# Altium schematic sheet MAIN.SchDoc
size A2
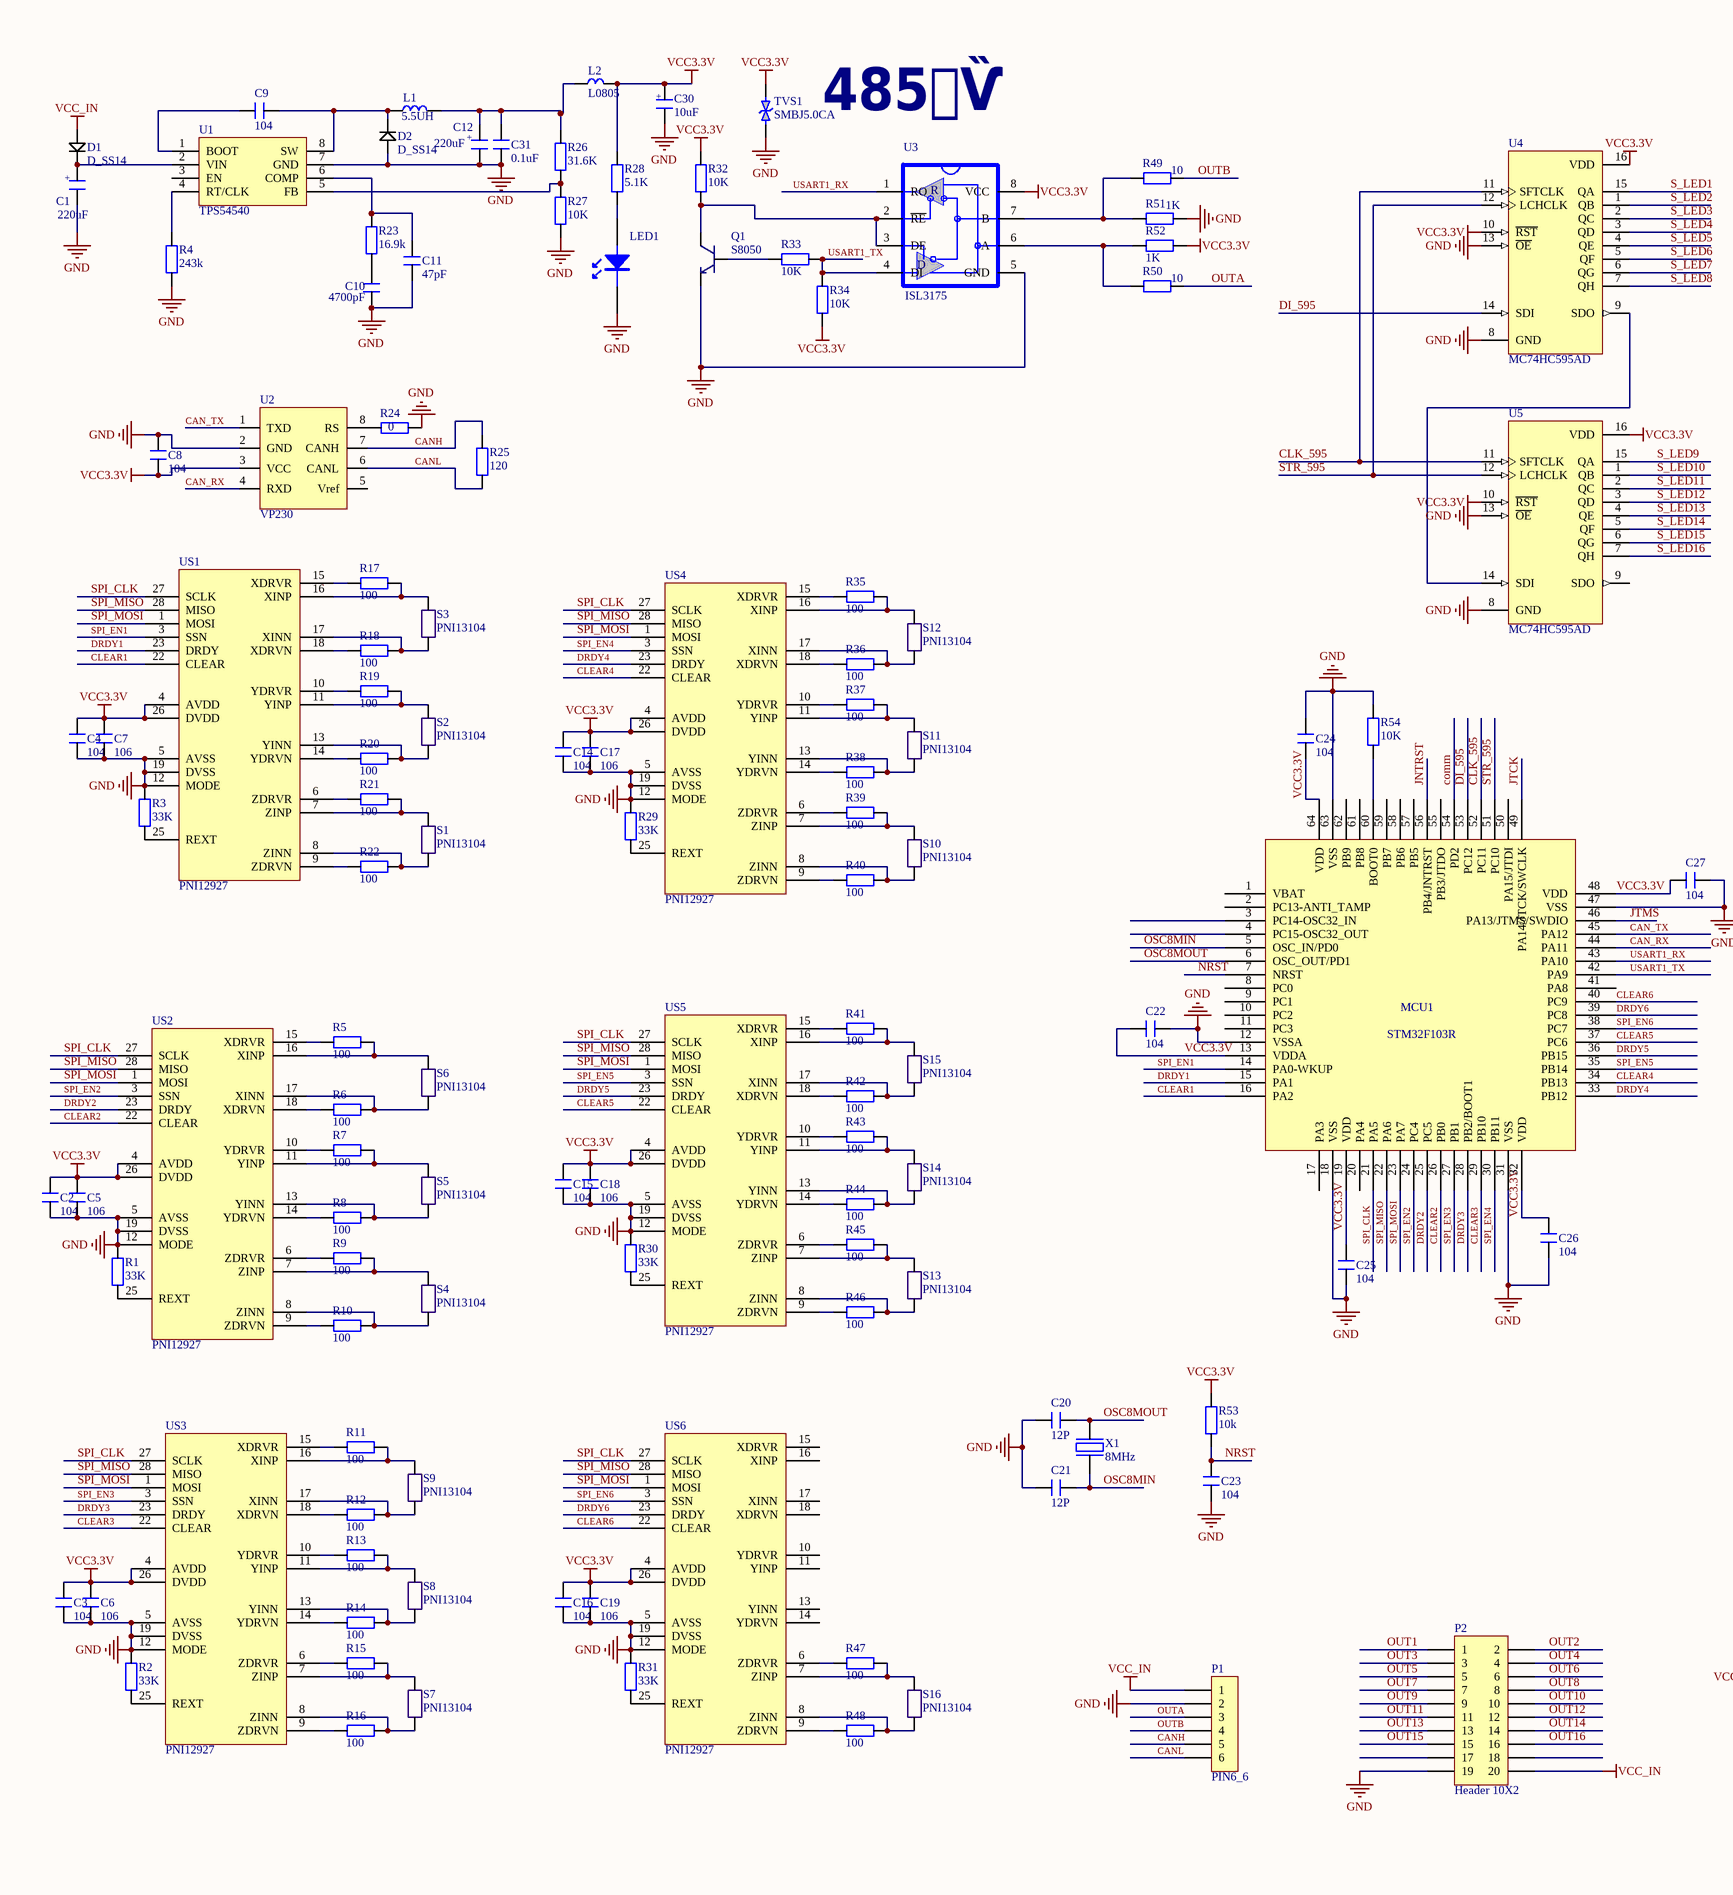
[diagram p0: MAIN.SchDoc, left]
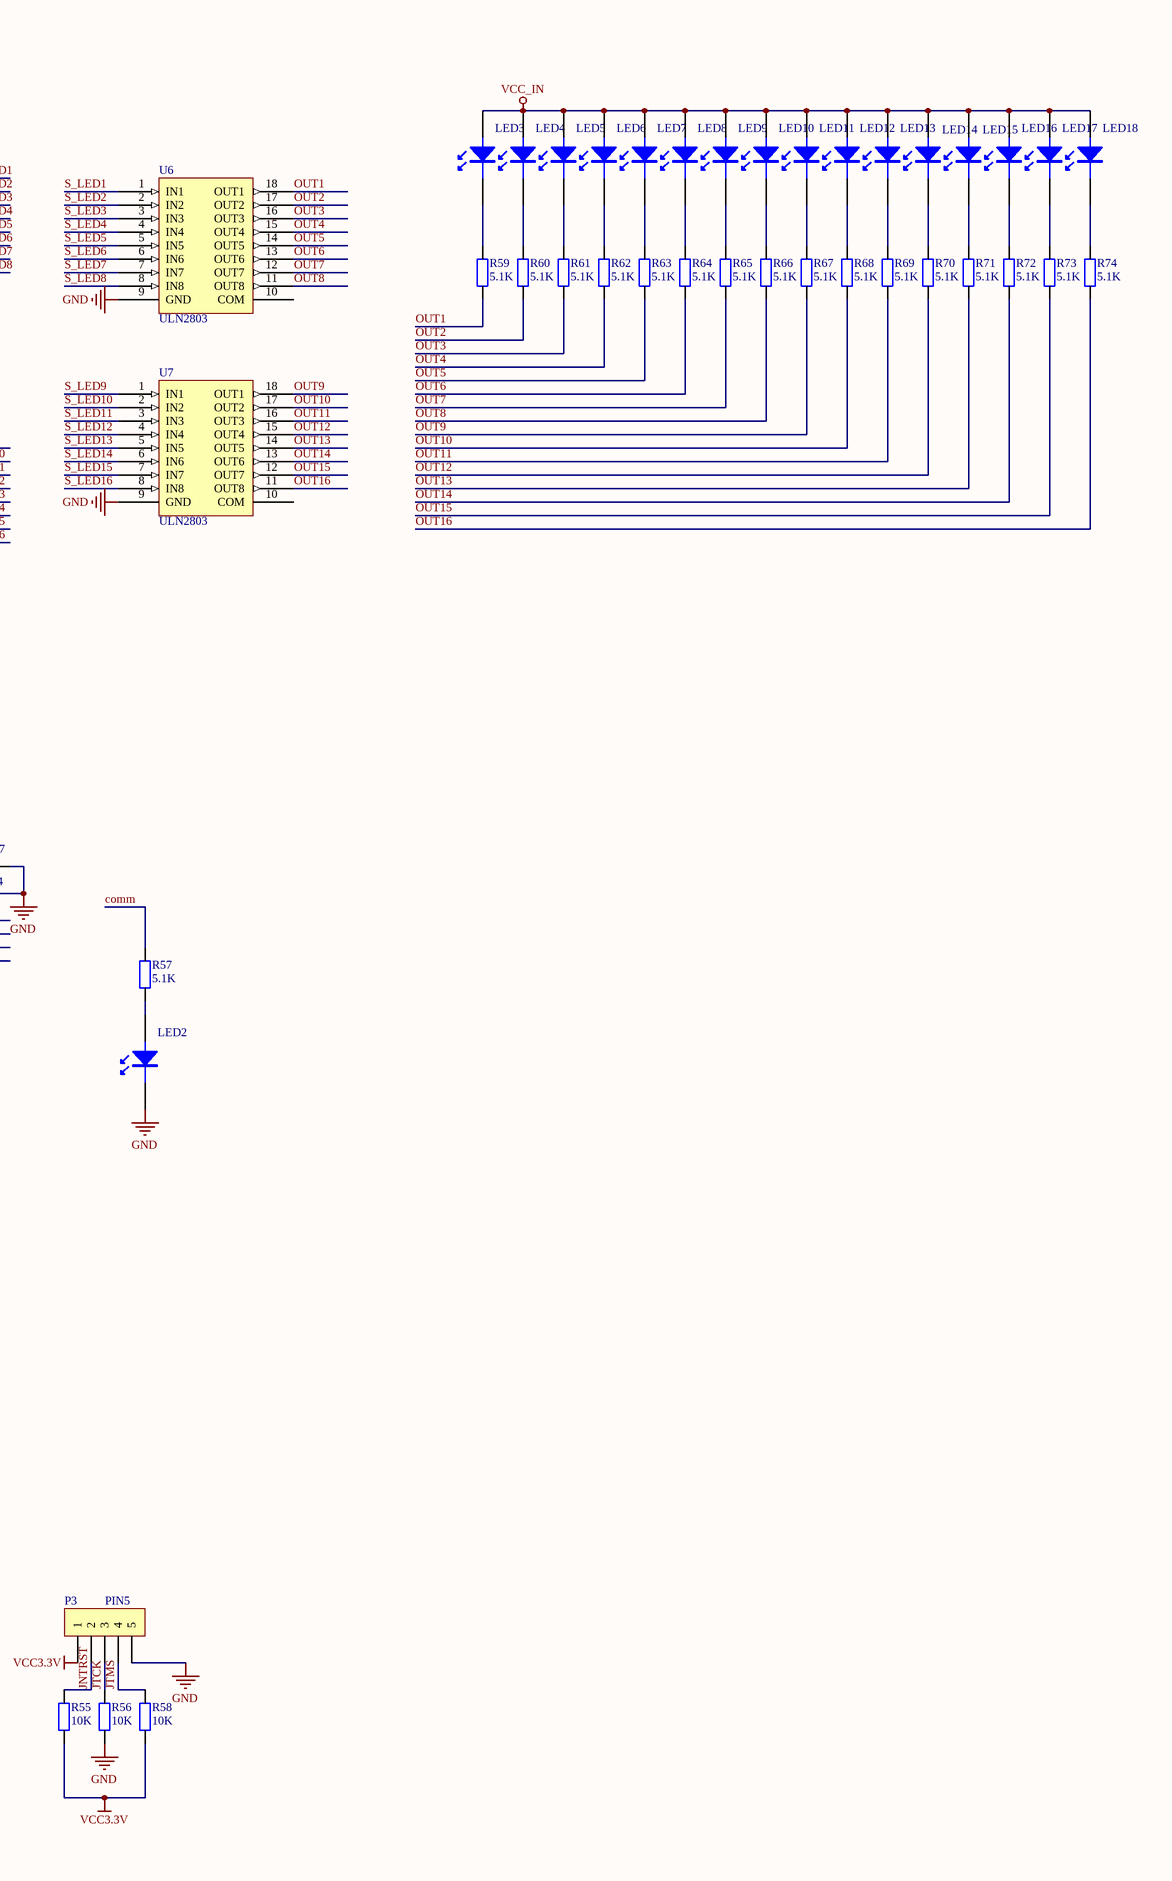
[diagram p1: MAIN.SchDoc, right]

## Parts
C1  220uF  [CAP_SMT_1]
C2  104  [C0603]
C3  104  [C0603]
C4  104  [C0603]
C5  106  [C0805]
C6  106  [C0805]
C7  106  [C0805]
C8  104  [C0603]
C9  104  [C0603]
C10  4700pF  [C0603]
C11  47pF  [C0603]
C12  220uF  [CAP_SMT_1]
C14  104  [C0603]
C15  104  [C0603]
C16  104  [C0603]
C17  106  [C0805]
C18  106  [C0805]
C19  106  [C0805]
C20  12P  [C0603]
C21  12P  [C0603]
C22  104  [C0603]
C23  104  [C0603]
C24  104  [C0603]
C25  104  [C0603]
C26  104  [C0603]
C27  104  [C0603]
C30  10uF  [C1206]
C31  0.1uF  [C0603]
D1  D_SS14  [D_3.0*5.0]
D2  D_SS14  [D_3.0*5.0]
L1  5.5UH  [L7*7]
L2  L0805  [L0805]
LED1  (no value)  [LED1-AK]
LED2  (no value)  [LED1-AK]
LED3  (no value)  [LED1-AK]
LED4  (no value)  [LED1-AK]
LED5  (no value)  [LED1-AK]
LED6  (no value)  [LED1-AK]
LED7  (no value)  [LED1-AK]
LED8  (no value)  [LED1-AK]
LED9  (no value)  [LED1-AK]
LED10  (no value)  [LED1-AK]
LED11  (no value)  [LED1-AK]
LED12  (no value)  [LED1-AK]
LED13  (no value)  [LED1-AK]
LED14  (no value)  [LED1-AK]
LED15  (no value)  [LED1-AK]
LED16  (no value)  [LED1-AK]
LED17  (no value)  [LED1-AK]
LED18  (no value)  [LED1-AK]
MCU1  STM32F103R  [TQFP64_STM32]
P1  PIN6_6  [KF350W_6]
P2  Header 10X2  [PIN20_10*2_2.54MM_1]
P3  PIN5  [PIN5_5*1_2.54MM_2]
Q1  S8050  [SOT-23]
R1  33K  [R0603]
R2  33K  [R0603]
R3  33K  [R0603]
R4  243k  [R0603]
R5  100  [R0603]
R6  100  [R0603]
R7  100  [R0603]
R8  100  [R0603]
R9  100  [R0603]
R10  100  [R0603]
R11  100  [R0603]
R12  100  [R0603]
R13  100  [R0603]
R14  100  [R0603]
R15  100  [R0603]
R16  100  [R0603]
R17  100  [R0603]
R18  100  [R0603]
R19  100  [R0603]
R20  100  [R0603]
R21  100  [R0603]
R22  100  [R0603]
R23  16.9k  [R0603]
R24  0  [R0603]
R25  120  [R0603]
R26  31.6K  [R0603]
R27  10K  [R0603]
R28  5.1K  [R0603]
R29  33K  [R0603]
R30  33K  [R0603]
R31  33K  [R0603]
R32  10K  [R0603]
R33  10K  [R0603]
R34  10K  [R0603]
R35  100  [R0603]
R36  100  [R0603]
R37  100  [R0603]
R38  100  [R0603]
R39  100  [R0603]
R40  100  [R0603]
R41  100  [R0603]
R42  100  [R0603]
R43  100  [R0603]
R44  100  [R0603]
R45  100  [R0603]
R46  100  [R0603]
R47  100  [R0603]
R48  100  [R0603]
R49  10  [R0603]
R50  10  [R0603]
R51  1K  [R0603]
R52  1K  [R0603]
R53  10k  [R0603]
R54  10K  [R0603]
R55  10K  [R0603]
R56  10K  [R0603]
R57  5.1K  [R0603]
R58  10K  [R0603]
R59  5.1K  [R0603]
R60  5.1K  [R0603]
R61  5.1K  [R0603]
R62  5.1K  [R0603]
R63  5.1K  [R0603]
R64  5.1K  [R0603]
R65  5.1K  [R0603]
R66  5.1K  [R0603]
R67  5.1K  [R0603]
R68  5.1K  [R0603]
R69  5.1K  [R0603]
R70  5.1K  [R0603]
R71  5.1K  [R0603]
R72  5.1K  [R0603]
R73  5.1K  [R0603]
R74  5.1K  [R0603]
S1  PNI13104  [PNI-13104]
S2  PNI13104  [PNI-13104]
S3  PNI13104  [PNI-13104]
S4  PNI13104  [PNI-13104]
S5  PNI13104  [PNI-13104]
S6  PNI13104  [PNI-13104]
S7  PNI13104  [PNI-13104]
S8  PNI13104  [PNI-13104]
S9  PNI13104  [PNI-13104]
S10  PNI13104  [PNI-13104]
S11  PNI13104  [PNI-13104]
S12  PNI13104  [PNI-13104]
S13  PNI13104  [PNI-13104]
S14  PNI13104  [PNI-13104]
S15  PNI13104  [PNI-13104]
S16  PNI13104  [PNI-13104]
TVS1  SMBJ5.0CA  [SMBJ6.5CA]
U1  TPS54540  [SOP8_1]
U2  VP230  [SOP8]
U3  ISL3175  [SO-8]
U4  MC74HC595AD  [SOP16]
U5  MC74HC595AD  [sop16]
U6  ULN2803  [SO-G18]
U7  ULN2803  [SO-G18]
US1  PNI12927  [MLF_28]
US2  PNI12927  [MLF_28]
US3  PNI12927  [MLF_28]
US4  PNI12927  [MLF_28]
US5  PNI12927  [MLF_28]
US6  PNI12927  [MLF_28]
X1  8MHz  [XTAL_49SMD]

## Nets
GND: C1.2 C2.1 C3.1 C4.1 C5.1 C6.1 C7.1 C8.2 C10.1 C11.1 C12.2 C14.1 C15.1 C16.1 C17.1 C18.1 C19.1 C20.1 C21.1 C22.2 C23.1 C24.2 C25.1 C26.1 C27.2 C30.2 C31.1 D2.1 LED1.K LED2.K MCU1.12(VSSA) MCU1.18(VSS) MCU1.31(VSS) MCU1.47(VSS) MCU1.63(VSS) P1.2 P2.19 P3.5 Q1.2 R1.2 R2.2 R3.2 R4.1 R24.2 R27.1 R29.2 R30.2 R31.2 R51.1 R54.2 R56.1 TVS1.1 U1.7(GND) U2.2(GND) U3.5(GND) U4.8(GND) U4.13(~{OE}) U5.8(GND) U5.13(~{OE}) U6.9(GND) U7.9(GND) US1.5(AVSS) US1.12(MODE) US1.19(DVSS) US2.5(AVSS) US2.12(MODE) US2.19(DVSS) US3.5(AVSS) US3.12(MODE) US3.19(DVSS) US4.5(AVSS) US4.12(MODE) US4.19(DVSS) US5.5(AVSS) US5.12(MODE) US5.19(DVSS) US6.5(AVSS) US6.12(MODE) US6.19(DVSS)
VCC3.3V: C2.2 C3.2 C4.2 C5.2 C6.2 C7.2 C8.1 C14.2 C15.2 C16.2 C17.2 C18.2 C19.2 C22.1 C24.1 C25.2 C26.2 C27.1 C30.1 L2.2 MCU1.13(VDDA) MCU1.19(VDD) MCU1.32(VDD) MCU1.48(VDD) MCU1.64(VDD) P3.1 R28.2 R32.1 R34.1 R52.1 R53.2 R55.1 R58.1 TVS1.2 U2.3(VCC) U3.8(VCC) U4.10(~{RST}) U4.16(VDD) U5.10(~{RST}) U5.16(VDD) US1.4(AVDD) US1.26(DVDD) US2.4(AVDD) US2.26(DVDD) US3.4(AVDD) US3.26(DVDD) US4.4(AVDD) US4.26(DVDD) US5.4(AVDD) US5.26(DVDD) US6.4(AVDD) US6.26(DVDD)
VCC_IN: D1.1 LED3.A LED4.A LED5.A LED6.A LED7.A LED8.A LED9.A LED10.A LED11.A LED12.A LED13.A LED14.A LED15.A LED16.A LED17.A LED18.A P1.1 P2.20
CAN_RX: MCU1.44(PA11) U2.4(RXD)
CAN_TX: MCU1.45(PA12) U2.1(TXD)
CANH: P1.5 R25.2 U2.7(CANH)
CANL: P1.6 R25.1 U2.6(CANL)
CLEAR1: MCU1.16(PA2) US1.22(CLEAR)
CLEAR2: MCU1.26(PB0) US2.22(CLEAR)
CLEAR3: MCU1.29(PB10) US3.22(CLEAR)
CLEAR4: MCU1.34(PB13) US4.22(CLEAR)
CLEAR5: MCU1.37(PC6) US5.22(CLEAR)
CLEAR6: MCU1.40(PC9) US6.22(CLEAR)
CLK_595: MCU1.52(PC11) U4.11(SFTCLK) U5.11(SFTCLK)
comm: MCU1.54(PD2) R57.2
DI_595: MCU1.53(PC12) U4.14(SDI)
DRDY1: MCU1.15(PA1) US1.23(DRDY)
DRDY2: MCU1.25(PC5) US2.23(DRDY)
DRDY3: MCU1.28(PB2/BOOT1) US3.23(DRDY)
DRDY4: MCU1.33(PB12) US4.23(DRDY)
DRDY5: MCU1.36(PB15) US5.23(DRDY)
DRDY6: MCU1.39(PC8) US6.23(DRDY)
JNTRST: MCU1.56(PB4/JNTRST) P3.2 R55.2
JTCK: MCU1.49(PA14/JTCK/SWCLK) P3.3 R56.2
JTMS: MCU1.46(PA13/JTMS/SWDIO) P3.4 R58.2
NRST: C23.2 MCU1.7(NRST) R53.1
OSC8MIN: C21.2 MCU1.5(OSC_IN/PD0) X1.1
OSC8MOUT: C20.2 MCU1.6(OSC_OUT/PD1) X1.2
OUT1: P2.1 R59.1 U6.18(OUT1)
OUT2: P2.2 R60.1 U6.17(OUT2)
OUT3: P2.3 R61.1 U6.16(OUT3)
OUT4: P2.4 R62.1 U6.15(OUT4)
OUT5: P2.5 R63.1 U6.14(OUT5)
OUT6: P2.6 R64.1 U6.13(OUT6)
OUT7: P2.7 R65.1 U6.12(OUT7)
OUT8: P2.8 R66.1 U6.11(OUT8)
OUT9: P2.9 R67.1 U7.18(OUT1)
OUT10: P2.10 R68.1 U7.17(OUT2)
OUT11: P2.11 R69.1 U7.16(OUT3)
OUT12: P2.12 R70.1 U7.15(OUT4)
OUT13: P2.13 R71.1 U7.14(OUT5)
OUT14: P2.14 R72.1 U7.13(OUT6)
OUT15: P2.15 R73.1 U7.12(OUT7)
OUT16: P2.16 R74.1 U7.11(OUT8)
OUTA: P1.3 R50.1
OUTB: P1.4 R49.1
S_LED1: U4.15(QA) U6.1(IN1)
S_LED2: U4.1(QB) U6.2(IN2)
S_LED3: U4.2(QC) U6.3(IN3)
S_LED4: U4.3(QD) U6.4(IN4)
S_LED5: U4.4(QE) U6.5(IN5)
S_LED6: U4.5(QF) U6.6(IN6)
S_LED7: U4.6(QG) U6.7(IN7)
S_LED8: U4.7(QH) U6.8(IN8)
S_LED9: U5.15(QA) U7.1(IN1)
S_LED10: U5.1(QB) U7.2(IN2)
S_LED11: U5.2(QC) U7.3(IN3)
S_LED12: U5.3(QD) U7.4(IN4)
S_LED13: U5.4(QE) U7.5(IN5)
S_LED14: U5.5(QF) U7.6(IN6)
S_LED15: U5.6(QG) U7.7(IN7)
S_LED16: U5.7(QH) U7.8(IN8)
SPI_CLK: MCU1.21(PA5) US1.27(SCLK) US2.27(SCLK) US3.27(SCLK) US4.27(SCLK) US5.27(SCLK) US6.27(SCLK)
SPI_EN1: MCU1.14(PA0-WKUP) US1.3(SSN)
SPI_EN2: MCU1.24(PC4) US2.3(SSN)
SPI_EN3: MCU1.27(PB1) US3.3(SSN)
SPI_EN4: MCU1.30(PB11) US4.3(SSN)
SPI_EN5: MCU1.35(PB14) US5.3(SSN)
SPI_EN6: MCU1.38(PC7) US6.3(SSN)
SPI_MISO: MCU1.22(PA6) US1.28(MISO) US2.28(MISO) US3.28(MISO) US4.28(MISO) US5.28(MISO) US6.28(MISO)
SPI_MOSI: MCU1.23(PA7) US1.1(MOSI) US2.1(MOSI) US3.1(MOSI) US4.1(MOSI) US5.1(MOSI) US6.1(MOSI)
STR_595: MCU1.51(PC10) U4.12(LCHCLK) U5.12(LCHCLK)
USART1_RX: MCU1.43(PA10) U3.1(RO)
USART1_TX: MCU1.42(PA9) R33.1 R34.2 U3.4(DI)
NetC1_1: C1.1 D1.2 U1.2(VIN)
NetC9_1: C9.1 D2.2 L1.1 U1.8(SW)
NetC9_2: C9.2 U1.1(BOOT)
NetC10_2: C10.2 R23.1
NetC11_2: C11.2 R23.2 U1.6(COMP)
NetC12_1: C12.1 C31.2 L1.2 L2.1 R26.2
NetLED1_A: LED1.A R28.1
NetLED2_A: LED2.A R57.1
NetLED3_K: LED3.K R59.2
NetLED4_K: LED4.K R60.2
NetLED5_K: LED5.K R61.2
NetLED6_K: LED6.K R62.2
NetLED7_K: LED7.K R63.2
NetLED8_K: LED8.K R64.2
NetLED9_K: LED9.K R65.2
NetLED10_K: LED10.K R66.2
NetLED11_K: LED11.K R67.2
NetLED12_K: LED12.K R68.2
NetLED13_K: LED13.K R69.2
NetLED14_K: LED14.K R70.2
NetLED15_K: LED15.K R71.2
NetLED16_K: LED16.K R72.2
NetLED17_K: LED17.K R73.2
NetLED18_K: LED18.K R74.2
NetMCU1_60: MCU1.60(BOOT0) R54.1
NetQ1_1: Q1.1 R33.2
NetQ1_3: Q1.3 R32.2 U3.2(~{RE}) U3.3(DE)
NetR1_1: R1.1 US2.25(REXT)
NetR2_1: R2.1 US3.25(REXT)
NetR3_1: R3.1 US1.25(REXT)
NetR4_2: R4.2 U1.4(RT/CLK)
NetR5_1: R5.1 US2.15(XDRVR)
NetR5_2: R5.2 S6.2 US2.16(XINP)
NetR6_1: R6.1 US2.18(XDRVN)
NetR6_2: R6.2 S6.1 US2.17(XINN)
NetR7_1: R7.1 US2.10(YDRVR)
NetR7_2: R7.2 S5.2 US2.11(YINP)
NetR8_1: R8.1 US2.14(YDRVN)
NetR8_2: R8.2 S5.1 US2.13(YINN)
NetR9_1: R9.1 US2.6(ZDRVR)
NetR9_2: R9.2 S4.2 US2.7(ZINP)
NetR10_1: R10.1 US2.9(ZDRVN)
NetR10_2: R10.2 S4.1 US2.8(ZINN)
NetR11_1: R11.1 US3.15(XDRVR)
NetR11_2: R11.2 S9.2 US3.16(XINP)
NetR12_1: R12.1 US3.18(XDRVN)
NetR12_2: R12.2 S9.1 US3.17(XINN)
NetR13_1: R13.1 US3.10(YDRVR)
NetR13_2: R13.2 S8.2 US3.11(YINP)
NetR14_1: R14.1 US3.14(YDRVN)
NetR14_2: R14.2 S8.1 US3.13(YINN)
NetR15_1: R15.1 US3.6(ZDRVR)
NetR15_2: R15.2 S7.2 US3.7(ZINP)
NetR16_1: R16.1 US3.9(ZDRVN)
NetR16_2: R16.2 S7.1 US3.8(ZINN)
NetR17_1: R17.1 US1.15(XDRVR)
NetR17_2: R17.2 S3.2 US1.16(XINP)
NetR18_1: R18.1 US1.18(XDRVN)
NetR18_2: R18.2 S3.1 US1.17(XINN)
NetR19_1: R19.1 US1.10(YDRVR)
NetR19_2: R19.2 S2.2 US1.11(YINP)
NetR20_1: R20.1 US1.14(YDRVN)
NetR20_2: R20.2 S2.1 US1.13(YINN)
NetR21_1: R21.1 US1.6(ZDRVR)
NetR21_2: R21.2 S1.2 US1.7(ZINP)
NetR22_1: R22.1 US1.9(ZDRVN)
NetR22_2: R22.2 S1.1 US1.8(ZINN)
NetR24_1: R24.1 U2.8(RS)
NetR26_1: R26.1 R27.2 U1.5(FB)
NetR29_1: R29.1 US4.25(REXT)
NetR30_1: R30.1 US5.25(REXT)
NetR31_1: R31.1 US6.25(REXT)
NetR35_1: R35.1 US4.15(XDRVR)
NetR35_2: R35.2 S12.2 US4.16(XINP)
NetR36_1: R36.1 US4.18(XDRVN)
NetR36_2: R36.2 S12.1 US4.17(XINN)
NetR37_1: R37.1 US4.10(YDRVR)
NetR37_2: R37.2 S11.2 US4.11(YINP)
NetR38_1: R38.1 US4.14(YDRVN)
NetR38_2: R38.2 S11.1 US4.13(YINN)
NetR39_1: R39.1 US4.6(ZDRVR)
NetR39_2: R39.2 S10.2 US4.7(ZINP)
NetR40_1: R40.1 US4.9(ZDRVN)
NetR40_2: R40.2 S10.1 US4.8(ZINN)
NetR41_1: R41.1 US5.15(XDRVR)
NetR41_2: R41.2 S15.2 US5.16(XINP)
NetR42_1: R42.1 US5.18(XDRVN)
NetR42_2: R42.2 S15.1 US5.17(XINN)
NetR43_1: R43.1 US5.10(YDRVR)
NetR43_2: R43.2 S14.2 US5.11(YINP)
NetR44_1: R44.1 US5.14(YDRVN)
NetR44_2: R44.2 S14.1 US5.13(YINN)
NetR45_1: R45.1 US5.6(ZDRVR)
NetR45_2: R45.2 S13.2 US5.7(ZINP)
NetR46_1: R46.1 US5.9(ZDRVN)
NetR46_2: R46.2 S13.1 US5.8(ZINN)
NetR47_1: R47.1 US6.6(ZDRVR)
NetR47_2: R47.2 S16.2 US6.7(ZINP)
NetR48_1: R48.1 US6.9(ZDRVN)
NetR48_2: R48.2 S16.1 US6.8(ZINN)
NetR49_2: R49.2 R51.2 U3.7(B)
NetR50_2: R50.2 R52.2 U3.6(A)
NetU4_9: U4.9(SDO) U5.14(SDI)

Not connected (* = marked no-connect by the designer): MCU1 1(VBAT) 2(PC13-ANTI_TAMP) 3(PC14-OSC32_IN) 4(PC15-OSC32_OUT) 8(PC0) 9(PC1) 10(PC2) 11(PC3) 17(PA3) 20(PA4) 41(PA8) 50(PA15/JTDI) 55(PB3/JTDO) 57(PB5) 58(PB6) 59(PB7) 61(PB8) 62(PB9); P2 17 18; U1 3(EN); U2 5(Vref); U5 9(SDO); U6 10(COM); U7 10(COM); US6 10(YDRVR) 11(YINP) 13(YINN) 14(YDRVN) 15(XDRVR) 16(XINP) 17(XINN) 18(XDRVN)

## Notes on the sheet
- 485ͨѶ

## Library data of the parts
C1 C12 = CAP_SMT_1
C2-C4 C8-C11 C14-C16 C20-C27 C31 = CAP_SMT_0603
C5-C7 C17-C19 = CAP_SMT_0805
C30 = CAP_SMT_1206
L1 = L_SMT_7*7*4
L2 = L_SMT_0805
LED1-LED18 = LED
MCU1 = STM32F103RXX_64
P1 = PIN6_6*1_3.81MM
P2 = Header 10X2: Header, 10-Pin, Dual row
P3 = PIN5_5*1_2.54mm
Q1 = QS8050
R1-R74 = RES_SMT_0603
TVS1 = TVS: 片式瞬态抑制二极管
U3 = MAX485
U4 U5 = MC74HC595AD: 8-Bit Serial-Input/Serial or Prallel-Output Shift Register with Latched 3-State Outputs
X1 = XTAL_49SMD: 假贴片晶振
